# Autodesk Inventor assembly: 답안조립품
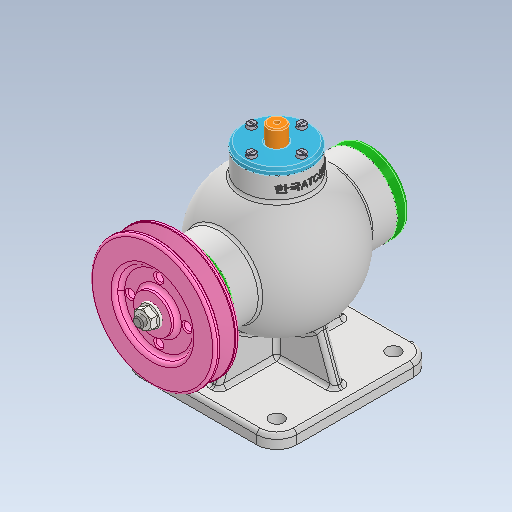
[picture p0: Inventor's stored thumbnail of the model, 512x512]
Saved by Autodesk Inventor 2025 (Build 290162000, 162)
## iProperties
Created: 2024-07
Part Number: 답안조립품
Document SubType Name: Assembly
Designer: 미서니
Author: 미서니
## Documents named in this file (15)
- C:\Users\미서니\OneDrive\바탕 화면\740708V1005\답안조립품.iam
- C:\Users\미서니\OneDrive\바탕 화면\740708V1005\본체.ipt
- C:\Users\미서니\OneDrive\바탕 화면\740708V1005\베어링- 6202\베어링- 6202.ipt
- C:\Users\미서니\OneDrive\바탕 화면\740708V1005\뒤커버\뒤커버.ipt
- C:\Users\미서니\OneDrive\바탕 화면\740708V1005\앞커버\앞커버.ipt
- C:\Users\미서니\OneDrive\바탕 화면\740708V1005\상부커버\상부커버.ipt
- C:\Users\미서니\OneDrive\바탕 화면\740708V1005\칼라\칼라.ipt
- C:\Users\미서니\OneDrive\바탕 화면\740708V1005\편심축\편심축.ipt
- C:\Users\미서니\OneDrive\바탕 화면\740708V1005\키 4 x 4 x 12\키 4 x 4 x 12.ipt
- C:\Users\미서니\OneDrive\바탕 화면\740708V1005\오일실 15 30 7\오일실 15 30 7.ipt
- C:\Users\미서니\OneDrive\바탕 화면\740708V1005\V-벨트풀리\V-벨트풀리.ipt
- C:\Users\미서니\OneDrive\바탕 화면\740708V1005\너트 M8\너트 M8.ipt
- C:\Users\미서니\OneDrive\바탕 화면\740708V1005\볼트 M4 x 16\볼트 M4 x 16.ipt
- C:\Users\미서니\OneDrive\바탕 화면\740708V1005\볼트 M4 x 12\볼트 M4 x 12.ipt
- C:\Users\미서니\OneDrive\바탕 화면\740708V1005\슬라이드\슬라이드.ipt
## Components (1 placed, 1 different names)
1. V-벨트풀리:1
